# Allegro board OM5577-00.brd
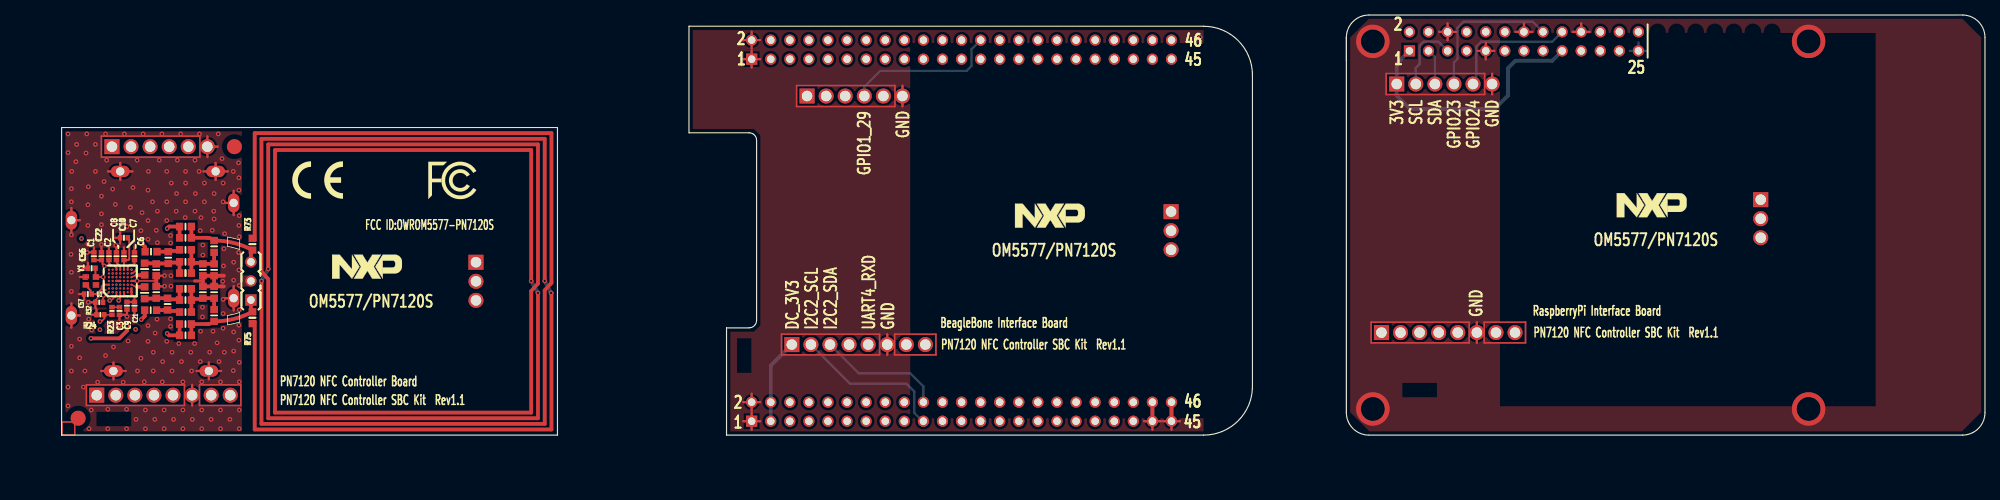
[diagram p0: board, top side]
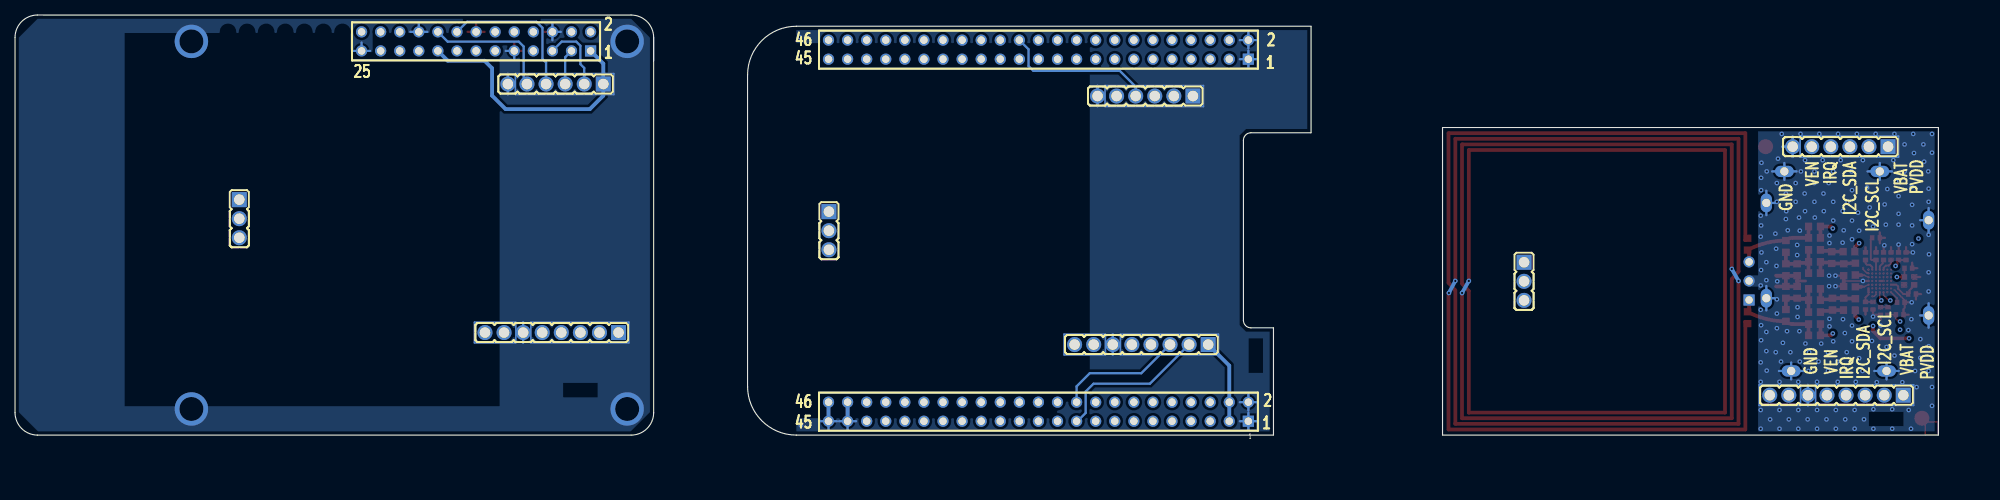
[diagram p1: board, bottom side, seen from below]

Outline 256 x 56 mm; copper layers: TOP, IS1, IS2, BOTTOM. Coordinates in mm from the lower left corner of the outline.
Outline path: 171,53 arc(171.88,55.12) 174,56 253,56 arc(255.12,55.12) 256,53 256,3 arc(255.12,0.88) 253,0 174,0 arc(171.88,0.88) 171,3 171,53 ; 171,53 171,49.9 ; 0,41 66,41 66,0 0,0 0,41 ; 83.5,54.5 83.5,40.3 91.5,40.3 arc(92.21,40.01) 92.5,39.3 92.5,15.3 arc(92.21,14.59) 91.5,14.3 88.5,14.3 88.5,0 152,0 arc(156.6,1.9) 158.5,6.5 158.5,48 arc(156.6,52.6) 152,54.5 83.5,54.5

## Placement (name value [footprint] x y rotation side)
1  BUBBLE1  [BUBBLE_DIAM8]  -6.2 8.1 0 top
2  BUBBLE2  [BUBBLE_DIAM8]  85.6 27.6 0 top
3  BUBBLE3  [BUBBLE_DIAM8]  209.95 -6.65 0 top
4  BUBBLE4(x4)  [BUBBLE_DIAM8]  175.15 -6.35 0 top
5  BUBBLE5(x4)  [BUBBLE_DIAM8]  183.35 -6.2 0 top
6  BUBBLE6(x4)  [BUBBLE_DIAM8]  191.55 -6.2 0 top
C1  1uF  [C0402]  4.3 23.85 90 top
C2  4.7uF  [C0402]  6.3 23.85 90 top
C3  1uF  [C0402]  7.7 16.55 270 top
C6  100nF  [C0402]  9.7 23.85 90 top
C7  1uF  [C0402]  8.3 23.85 90 top
C8  470nF  [C0402]  7.3 23.85 90 top
C9  100nF  [C0402]  8.7 17.25 270 top
C10  NC  [C0402]  8.3 26.3 180 top
C11  39pF/50V  [C0603]  16.49 14.8 0 top
C12  39pF/50V  [C0603]  16.49 26.3 0 top
C13  180pF  [C0603]  12.6 19.04 90 top
C14  180pF  [C0603]  12.6 22.04 90 top
C15  18pF/50V  [C0603]  16.49 18 0 top
C16  18pF/50V  [C0603]  16.49 23.1 0 top
C17  10pF/50V  [C0603]  20.3 19.04 90 top
C18  10pF/50V  [C0603]  20.3 22.04 90 top
C19  1nF/16V  [C0603]  11.85 16.65 0 top
C20  1nF/16V  [C0603]  11.9 24.45 0 top
C21  1uF  [C0402]  9.7 17.25 270 top
C22  100nF  [C0402]  5.3 23.85 90 top
C50  NC  [C0603]  18.8 19.04 90 top
C51  NC  [C0603]  18.8 22.04 90 top
C52  NC  [C0603]  16.49 27.8 0 top
C53  NC  [C0603]  16.49 13.3 0 top
C54  NC  [C0603]  16.49 19.5 0 top
C55  NC  [C0603]  16.49 21.6 0 top
C56  10pF/50V  [C0402]  4 22.25 180 top
C57  10pF/50V  [C0402]  3.5 18.8 180 top
J1  bar_2x13_FD_RASPBERRY  [BAR_2X13_FD_SPE_RASPBERRY]  179.4 51.21 0 top
J8  bar_2x23_MD_beaglebone_p8  [BAR_2X23_SPE_BEAGLEBONE]  91.84 50.11 0 top
J9  bar_2x23_MD_beaglebone_p9  [BAR_2X23_SPE_BEAGLEBONE]  91.84 1.85 0 top
L1  560nH  [SELF_0603]  11.05 18.97 270 top
L2  560nH  [SELF_0603]  11.05 22.13 90 top
L104  Antenna  [ANTENNA_4T_40X40]  23.75 20.55 180 top
NOREF  -  []  131.6 29.25 0 top
NOREF#2  -  []  211.7 30.65 0 top
NOREF#3  -  []  40.7 22.45 0 top
NOREF#4  -  []  32.1 122.75 0 top
NOREF#5  -  [unnamed#2]  23 38.45 0 top
NOREF#6  -  []  51.3 33.95 0 top
NOREF#7  -  []  33.2 34 0 top
NOREF#8  -  [unnamed#2]  2.2 2.25 0 top
R1  2K4  [R0603]  14.1 17.46 270 top
R2  2K4  [R0603]  14.2 23.66 270 top
R23  NC  [0402R]  6.7 16.55 90 top
R24  100K  [0402R]  5.15 16.05 0 top
R32  100K  [0402R]  5 17.7 0 top
R53  NC  [R0603]  16.49 16.4 0 top
R54  NC  [R0603]  16.49 24.7 0 top
R55  3R3  [R0603]  20.3 15.95 270 top
R56  3R3  [R0603]  20.3 25.15 90 top
R73  0R  [R0603]  25.4 25.45 90 top
R75  0R  [R0603]  25.4 15.65 270 top
SH1  Shield_27x22mm  [SHIELD_27X22]  1.3 35.15 270 top
TB1  NC  [BAR_1X3_MD]  25.2 18.01 90 top
TB2  FORK  [AGPS1-08-BCZ-1MM3]  4.67 5.32 0 bottom
TB3  FORK  [AGPS1-06-BCZ-1MM3]  6.7 38.45 0 bottom
TB4  FORK  [AGPS1-08-BSE]  175.67 13.67 0 bottom
TB5  FORK  [AGPS1-06-BSE]  177.7 46.8 0 bottom
TB8  FORK  [AGPS1-06-BSE]  99.22 45.2 0 bottom
TB9  FORK  [AGPS1-08-BSE]  97.19 12.07 0 bottom
TB10  FORK  [AGPS1-03-BCZ-1MM3]  55.15 23.04 270 bottom
TB11  FORK  [AGPS1-03-BSE]  147.67 29.79 270 bottom
TB12  FORK  [AGPS1-03-BSE]  226.15 31.39 270 bottom
U1  PN7120  [VFBGA49_050_SOT1320-1]  7.8 20.55 180 top
Y1  NX2016AA_27.12Mhz  [NX2016AA]  3.9 20.55 180 top

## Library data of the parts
1-3 = BUBBLE_CI: alternate symbols: (BUBBLE_DIAM4)
4 = BUBBLE_entretoise_nylon_M3x20: alternate symbols: (BUBBLE_DIAM4)
5 = BUBBLE_RONDELLE_M3_PLATE: alternate symbols: (BUBBLE_DIAM4)
6 = BUBBLE_VIS_M3X6: alternate symbols: (BUBBLE_DIAM4)
C1-C3 C6-C10 C21 C22 C56 C57 = CAP NP: User Part Number: BCNNUMBER; Tolerance: TOLERANCE
C11-C20 C50-C55 = CAP NP: Tolerance: TOLERANCE; User Part Number: PARTNUM
J1 = bar_2x13_FD_RASPBERRY_0: Tolerance: TOLERANCE; User Part Number: PARTNUM
J8 = bar_2x23_MD_beaglebone_p8: Tolerance: TOLERANCE; User Part Number: PARTNUM
J9 = bar_2x23_MD_beaglebone_p9_1: Tolerance: TOLERANCE; User Part Number: PARTNUM
L1 L2 = INDUCTOR: User Part Number: PARTNUM; Tolerance: TOLERANCE
L104 = Antenna
R1 R2 R53-R56 R73 R75 = RESISTOR: User Part Number: PARTNUM; Tolerance: TOLERANCE
R23 R24 R32 = RESISTOR_0: Tolerance: TOLERANCE; User Part Number: BCNNUMBER
SH1 = OM5782 Shield_1
TB1 TB10-TB12 = bar_1x3_MD: Tolerance: TOLERANCE; User Part Number: PARTNUM
TB2 TB4 TB9 = bar_1x8_MD: Tolerance: TOLERANCE; User Part Number: PARTNUM
TB3 TB5 TB8 = bar_1x6_MD: Tolerance: TOLERANCE; User Part Number: PARTNUM
U1 = PN7120_VFBGA49
Y1 = NX2016AA_xMhz

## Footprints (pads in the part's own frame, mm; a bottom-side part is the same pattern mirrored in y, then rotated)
0402R
  rect 0.61x0.711 smd: 1(-0.508,0) 2(0.508,0)
AGPS1-03-BCZ-1MM3
  rect 2x2 hole 1.4: 1(0,0)
  round 2 hole 1.4: 2(2.54,0) 3(5.08,0)
AGPS1-03-BSE
  rect 2x2 hole 1.4: 1(0,0)
  round 2 hole 1.4: 2(2.54,0) 3(5.08,0)
AGPS1-06-BCZ-1MM3
  rect 2x2 hole 1.4: 1(0,0)
  round 2 hole 1.4: 2(2.54,0) 3(5.08,0) 4(7.62,0) 5(10.16,0) 6(12.7,0)
AGPS1-06-BSE
  rect 2x2 hole 1.4: 1(0,0)
  round 2 hole 1.4: 2(2.54,0) 3(5.08,0) 4(7.62,0) 5(10.16,0) 6(12.7,0)
AGPS1-08-BCZ-1MM3
  rect 2x2 hole 1.4: 1(0,0)
  round 2 hole 1.4: 2(2.54,0) 3(5.08,0) 4(7.62,0) 5(10.16,0) 6(12.7,0) 7(15.24,0) 8(17.78,0)
AGPS1-08-BSE
  rect 2x2 hole 1.4: 1(0,0)
  round 2 hole 1.4: 2(2.54,0) 3(5.08,0) 4(7.62,0) 5(10.16,0) 6(12.7,0) 7(15.24,0) 8(17.78,0)
ANTENNA_4T_40X40
  round 0.5 smd: 1(-1.95,5.45) 2(-1.95,-5.45)
BAR_1X3_MD
  rect 1.49x1.49 hole 1: 1(0,0)
  round 1.49 hole 1: 2(2.54,0) 3(5.08,0)
BAR_2X13_FD_SPE_RASPBERRY
  rect 1.49x1.49 hole 1: 1(0,0)
  round 1.49 hole 1: 2(0,2.54) 3(2.54,0) 4(2.54,2.54) 5(5.08,0) 6(5.08,2.54) 7(7.62,0) 8(7.62,2.54) 9(10.16,0) 10(10.16,2.54) 11(12.7,0) 12(12.7,2.54) 13(15.24,0) 14(15.24,2.54) 15(17.78,0) 16(17.78,2.54) 17(20.32,0) 18(20.32,2.54) 19(22.86,0) 20(22.86,2.54) 21(25.4,0) 22(25.4,2.54) 23(27.94,0) 24(27.94,2.54) 25(30.48,0) 26(30.48,2.54)
BAR_2X23_SPE_BEAGLEBONE
  rect 1.49x1.49 hole 1: C1(0,0)
  round 1.49 hole 1: C2(0,2.54) C3(2.54,0) C4(2.54,2.54) C5(5.08,0) C6(5.08,2.54) C7(7.62,0) C8(7.62,2.54) C9(10.16,0) C10(10.16,2.54) C11(12.7,0) C12(12.7,2.54) C13(15.24,0) C14(15.24,2.54) C15(17.78,0) C16(17.78,2.54) C17(20.32,0) C18(20.32,2.54) C19(22.86,0) C20(22.86,2.54) C21(25.4,0) C22(25.4,2.54) C23(27.94,0) C24(27.94,2.54) C25(30.48,0) C26(30.48,2.54) C27(33.02,0) C28(33.02,2.54) C29(35.56,0) C30(35.56,2.54) C31(38.1,0) C32(38.1,2.54) C33(40.64,0) C34(40.64,2.54) C35(43.18,0) C36(43.18,2.54) C37(45.72,0) C38(45.72,2.54) C39(48.26,0) C40(48.26,2.54) C41(50.8,0) C42(50.8,2.54) C43(53.34,0) C44(53.34,2.54) C45(55.88,0) C46(55.88,2.54)
BUBBLE_DIAM8
  round 0 smd: 1(0,0)
C0402
  rect 0.61x0.711 smd: 1(-0.508,0) 2(0.508,0)
C0603
  rect 0.965x1.016 smd: 1(-0.787,0) 2(0.787,0)
NX2016AA
  rect 0.85x0.75 smd: 1(-0.675,-0.525) 3(0.675,0.525) 4(-0.675,0.525)
  custom 0.188x0.188 smd: 2(0.675,-0.525)
R0603
  rect 0.965x1.016 smd: 1(-0.787,0) 2(0.787,0)
SELF_0603
  rect 0.965x1.016 smd: 1(-0.787,0) 2(0.787,0)
SHIELD_27X22
  oval 1.5x2.5 hole 1.1: 1(0,6.5) 4(26.6,5.6) 5(26.6,18.3) 8(0,19.2)
  oval 2.5x1.5 hole 1.1: 2(6.5,0) 3(19.2,0) 6(16.9,21.6) 7(4.2,21.6)
unnamed#2
  round 2 smd: (0,0)
VFBGA49_050_SOT1320-1
  round 0.3 smd: A1(1.5,1.5) A2(1.5,1) A3(1.5,0.5) A4(1.5,0) A5(1.5,-0.5) A6(1.5,-1) A7(1.5,-1.5) B1(1,1.5) B2(1,1) B3(1,0.5) B4(1,0) B5(1,-0.5) B6(1,-1) B7(1,-1.5) C1(0.5,1.5) C2(0.5,1) C3(0.5,0.5) C4(0.5,0) C5(0.5,-0.5) C6(0.5,-1) C7(0.5,-1.5) D1(0,1.5) D2(0,1) D3(0,0.5) D4(0,0) D5(0,-0.5) D6(0,-1) D7(0,-1.5) E1(-0.5,1.5) E2(-0.5,1) E3(-0.5,0.5) E4(-0.5,0) E5(-0.5,-0.5) E6(-0.5,-1) E7(-0.5,-1.5) F1(-1,1.5) F2(-1,1) F3(-1,0.5) F4(-1,0) F5(-1,-0.5) F6(-1,-1) F7(-1,-1.5) G1(-1.5,1.5) G2(-1.5,1) G3(-1.5,0.5) G4(-1.5,0) G5(-1.5,-0.5) G6(-1.5,-1) G7(-1.5,-1.5)

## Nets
5V: J1.2(5V)
GND: C1.2 C2.2 C3.2 C6.2 C7.2 C8.2 C9.2 C10.2 C13.2 C14.1 C17.2 C18.1 C21.2 C22.2 C50.2 C51.1 C56.2 C57.2 R24.1 R32.1 SH1.1 SH1.2 SH1.3 SH1.4 SH1.5 SH1.6 SH1.7 SH1.8 TB1.2 TB2.6 TB3.6 U1.B5(TST2) U1.B6(VSS1) U1.C2(PVSS) U1.C4(VSS) U1.D4(VSS2) U1.D6(VSS3) U1.E2(DCDC_VSS) U1.F3(VSS4) U1.G4(TVSS) Y1.2(#2) Y1.4(#4)
GND_2270869: J1.6(GND#6) J1.9(GND#9) J1.14(GND#14) J1.20(GND#20) J1.25(GND#25) TB4.6 TB5.6
GND_2272419: J8.C1(GND#C1) J8.C2(GND#C2) J9.C1(GND#C1) J9.C2(GND#C2) J9.C43(GND#C43) J9.C44(GND#C44) J9.C45(GND#C45) J9.C46(GND#C46) TB8.6 TB9.6
PVDD: C2.1 C3.1 C9.1 C21.1 R23.2 TB2.1 TB3.1 U1.C7(VBAT) U1.D3(PVDD) U1.G1(VBAT2) U1.G2(VUP)
VBAT_PVDD: J9.C3(DC_3V3#C3) J9.C4(DC_3V3#C4) TB9.1
VBAT_PVDD_2271009: J1.1(3V3#1) J1.17(3V3#17) TB5.1
VDD_5V: J9.C5(VDD_5V)
_5V: J1.4(_5V)
_SYS_5V: J9.C8(_SYS_5V)
_VDD_5V: J9.C6(_VDD_5V)
ANT1: C11.1 C53.1 U1.G7(ANT1)
ANT2: C12.1 C52.1 U1.G6(ANT2)
I2C_SCL: TB2.2 TB3.2 U1.B1(I2CSCL)
I2C_SCL_2270949: J1.5(SCL) TB5.2
I2C_SCL_2272419: J9.C19(I2C2_SCL) TB9.2
I2C_SDA: TB2.3 TB3.3 U1.C1(I2CSDA)
I2C_SDA_2270933: J1.3(SDA) TB5.3
I2C_SDA_2272319: J9.C20(I2C2_SDA) TB9.3
IRQ: TB2.4 TB3.4 U1.D1(IRQ)
IRQ_2270913: J1.16(GPIO23) TB5.4
IRQ_2273337: J8.C26(GPIO1_29) TB8.4
RXN: C20.1 U1.F5(RXN)
RXP: C19.1 U1.F6(RXP)
SYS_5V: J9.C7(SYS_5V)
TX1: L1.1 U1.G3(TX1)
TX2: L2.1 U1.G5(TX2)
VEN: TB2.5 TB3.5 U1.E1(VEN)
VEN_2270923: J1.18(GPIO24) TB5.5
VEN_2272419: J9.C11(UART4_RXD) TB9.5
N2189999: C15.2 C17.1 C50.1 C54.2 R53.2 R55.1
N2190055: C16.2 C18.2 C51.2 C55.2 R54.2 R56.1
N2190079: C13.1 C15.1 C54.1 L1.2 R1.1
N2190159: C12.2 C52.2 R56.2 R73.1 TB1.3
N2190199: C11.2 C53.2 R55.2 R75.1 TB1.1
N2190513: C14.2 C16.1 C55.1 L2.2 R2.2
N2190991: L104.1 L104.2 R73.2 R75.2
N2198580: R23.1 R24.2 U1.B2(I2CADR0)
N2222470: C20.2 R2.1 R54.1
N2227379: C19.2 R1.2 R53.1
N2256986: C57.1 U1.A3(XTAL1) Y1.3(#3)
N2256988: C56.1 U1.C3(XTAL2) Y1.1(#1)
N2257197: R32.2 U1.A1(TST1)
N2257995: C1.1 C22.1 U1.C6(VDD)
N2259746: C7.1 C10.1 U1.E7(TVDD)
N2259753: C8.1 U1.D7(VDHF)
N2259760: C6.1 U1.F7(VMID)

Pads without a net: 1 1; 2 1; 3 1; 4 1; 5 1; 6 1; J1 7 8 10 11 12 13 15 19 21 22 23 24 26; J8 C3 C4 C5 C6 C7 C8 C9 C10 C11 C12 C13 C14 C15 C16 C17 C18 C19 C20 C21 C22 C23 C24 C25 C27 C28 C29 C30 C31 C32 C33 C34 C35 C36 C37 C38 C39 C40 C41 C42 C43 C44 C45 C46; J9 C9 C10 C12 C13 C14 C15 C16 C17 C18 C21 C22 C23 C24 C25 C26 C27 C28 C29 C30 C31 C32 C33 C34 C35 C36 C37 C38 C39 C40 C41 C42; TB2 7 8; TB4 1 2 3 4 5 7 8; TB8 1 2 3 5; TB9 4 7 8; TB10 1 2 3; TB11 1 2 3; TB12 1 2 3; U1 A2 A4 A5 A6 A7 B3 B4 B7 C5 D2 D5 E3 E4 E5 E6 F1 F2 F4

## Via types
v1: diameter 0.62, hole 0.31, TOP to BOTTOM, 211 vias
v2: diameter 0.28, hole 0.1, TOP to IS1, 33 vias
v3: diameter 4.445, hole 3.2, TOP to BOTTOM, 4 vias

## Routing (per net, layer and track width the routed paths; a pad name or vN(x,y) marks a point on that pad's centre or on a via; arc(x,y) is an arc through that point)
GND: length 200.9
  TOP w0.2: v1(10.05,20.55) 12.6,20.55 ; R32.1 4.49,17.99 v2(4.9,18.4) v2(5.85,19.35)
  TOP w0.3: TB3.6 19.4,39.83 ; TB3.6 20.78,38.45 ; TB3.6 19.4,37.07 ; SH1.5 19.6,9.68 ; SH1.5 17.97,8.55 ; SH1.5 19.6,7.42 ; SH1.5 21.23,8.55 ; 3.57,24.36 C1.2 4.3,25.04 ; 18.87,35.15 SH1.8 ; SH1.8 22.13,35.15 ; SH1.8 20.5,34.02 ; SH1.8 20.5,36.28 ; C7.2 8.3,25.04 ; 3.49,22.98 C56.2 2.81,22.25 ; 21.77,30.95 SH1.7 ; SH1.7 22.9,32.58 ; SH1.7 22.9,29.32 ; 7.7,15.36 C3.2 8.43,16.04 ; 4.64,16.78 R24.1 3.96,16.05 ; 4.49,16.97 R32.1 3.81,17.7 ; SH1.4 8.53,8.55 ; SH1.4 6.9,7.42 ; SH1.4 6.9,9.68 ; SH1.4 5.27,8.55 ; 7.79,25.57 C10.2 ; C10.2 7.11,26.3 ; C10.2 7.79,27.03 ; C13.2 13.48,19.82 ; 8.7,16.06 C9.2 ; 21.77,18.25 SH1.6 ; SH1.6 22.9,19.88 ; SH1.6 22.9,16.62 ; C8.2 7.3,25.04 ; SH1.2 1.3,30.28 ; SH1.2 2.43,28.65 ; SH1.2 1.3,27.02 ; C2.2 6.3,25.04 ; 2.99,18.07 C57.2 2.31,18.8 ; C14.1 13.48,21.25 ; C6.2 9.7,25.04 ; 17.37,3.94 TB2.6 17.37,6.7 ; v2(7.3,20.55) U1.D4 ; SH1.1 9.43,35.15 ; SH1.1 7.8,34.02 ; SH1.1 6.17,35.15 ; SH1.1 7.8,36.28 ; C22.2 5.3,25.04 ; SH1.3 2.43,15.95 ; SH1.3 1.3,17.58 ; SH1.3 1.3,14.32 ; U1.G4 v1(10.05,20.55) ; 2.42,21.07 Y1.2 ; 9.7,16.06 C21.2
  TOP w0.4: 18.8,20.55 17.7,20.55
  TOP w0.5: C13.2 C14.1 ; C17.2 C50.2 C51.1 C18.1 ; C17.2 21.6,19.82 ; C17.2 C18.1 ; C18.1 21.6,21.25
  IS1 w0.3: 1.3,27.52 SH1.2 ; SH1.2 1.3,29.78 ; SH1.2 2.43,28.65 ; SH1.4 6.9,9.68 ; SH1.4 5.77,8.55 ; SH1.4 8.03,8.55 ; SH1.4 6.9,7.42 ; 19.37,35.15 SH1.8 ; SH1.8 20.5,36.28 ; SH1.8 21.63,35.15 ; SH1.8 20.5,34.02 ; 19.6,7.42 SH1.5 ; SH1.5 18.47,8.55 ; SH1.5 19.6,9.68 ; SH1.5 20.73,8.55 ; TB3.6 20.73,38.45 ; TB3.6 19.4,37.12 ; TB3.6 19.4,39.78 ; 1.3,14.82 SH1.3 ; SH1.3 2.43,15.95 ; SH1.3 1.3,17.08 ; 7.8,34.02 SH1.1 ; SH1.1 6.67,35.15 ; SH1.1 7.8,36.28 ; SH1.1 8.93,35.15 ; SH1.7 22.9,32.08 ; SH1.7 21.77,30.95 ; SH1.7 22.9,29.82 ; 17.37,6.65 TB2.6 17.37,3.99 ; 21.77,18.25 SH1.6 ; SH1.6 22.9,19.38 ; SH1.6 22.9,17.12
  IS2 w0.3: 5.77,8.55 SH1.4 ; SH1.4 8.03,8.55 ; SH1.4 6.9,9.68 ; SH1.4 6.9,7.42 ; TB3.6 19.4,39.78 ; TB3.6 19.4,37.12 ; TB3.6 20.73,38.45 ; 20.5,34.02 SH1.8 ; SH1.8 21.63,35.15 ; SH1.8 19.37,35.15 ; SH1.8 20.5,36.28 ; 17.37,3.99 TB2.6 17.37,6.65 ; SH1.5 20.73,8.55 ; SH1.5 19.6,9.68 ; SH1.5 19.6,7.42 ; SH1.5 18.47,8.55 ; SH1.6 22.9,19.38 ; SH1.6 22.9,17.12 ; SH1.6 21.77,18.25 ; 21.77,30.95 SH1.7 ; SH1.7 22.9,32.08 ; SH1.7 22.9,29.82 ; 6.67,35.15 SH1.1 ; SH1.1 8.93,35.15 ; SH1.1 7.8,34.02 ; 1.3,29.78 SH1.2 1.3,27.52 ; 1.3,17.08 SH1.3 1.3,14.82
  BOTTOM w0.3: SH1.5 19.6,9.68 ; SH1.5 19.6,7.42 ; SH1.5 21.23,8.55 ; SH1.5 17.97,8.55 ; 22.9,16.62 SH1.6 ; SH1.6 22.9,19.88 ; SH1.6 21.77,18.25 ; SH1.8 22.13,35.15 ; SH1.8 20.5,34.02 ; SH1.8 20.5,36.28 ; SH1.8 18.87,35.15 ; TB3.6 19.4,39.83 ; TB3.6 20.78,38.45 ; TB3.6 19.4,37.07 ; 17.37,3.94 TB2.6 17.37,6.7 ; SH1.3 1.3,17.58 ; SH1.3 2.43,15.95 ; SH1.3 1.3,14.32 ; 1.3,27.02 SH1.2 ; SH1.2 2.43,28.65 ; SH1.2 1.3,30.28 ; 22.9,29.32 SH1.7 ; SH1.7 22.9,32.58 ; SH1.7 21.77,30.95 ; 5.27,8.55 SH1.4 ; SH1.4 6.9,9.68 ; SH1.4 8.53,8.55 ; SH1.4 6.9,7.42 ; SH1.1 7.8,36.28 ; SH1.1 9.43,35.15 ; SH1.1 7.8,34.02 ; SH1.1 6.17,35.15
  vias: v1(0.85,40.15) v1(0.85,37.65) v1(0.85,6.4) v1(0.85,3.9) v1(1.25,24.1) v1(1.3,32.85) v1(1.3,31.1) v1(1.3,26.7) v1(1.3,21.7) v1(1.3,19.15) v1(1.3,11.85) v1(1.3,8.55) v1(1.35,35.15) v1(1.9,36.45) v1(2,38.75) v1(2.4,12.8) v1(2.4,10.3) v1(2.9,6.4) v1(3.1,8.55) v1(3.25,37.6) v1(3.35,40.15) v1(3.4,24.35) v1(3.55,33.1) v1(3.5,30.7) v1(3.5,27.95) v1(3.5,25.45) v1(3.55,17.7) v1(3.6,15.45) v1(3.65,0.85) v1(4,14) v1(3.95,3.35) v1(4.5,38.75) v1(4.5,35.15) v1(4.8,7.05) v1(5.3,31.85) v1(5.3,29.5) v1(5.3,28.05) v1(5.3,25.4) v1(5.65,33.8) v1(5.85,40.15) v1(5.85,10.6) v1(6,36.65) v1(6.15,3.45) v1(6.15,0.85) v1(6.8,32.8) v1(6.9,11.75) v1(7,28.05) v1(7.15,30.75) v1(7.2,25.3) v1(7.7,14.6) v1(8.2,7.05) v1(8.35,40.15) v1(8.7,27.8) v1(8.7,15.8) v1(8.65,3.45) v1(8.65,0.85) v1(8.85,12.55) v1(9.15,30.35) v1(9.5,33) v1(9.9,2.1) v1(10.05,36.65) v1(10.1,8.55) v1(10.55,27.25) v1(10.55,10.25) v1(10.7,29.65) v1(10.85,40.15) v1(11,7.1) v1(11.15,3.35) v1(11.15,0.85) v1(11.5,32.65) v1(11.5,28.6) v1(11.5,26.1) v1(11.5,14.6) v1(11.5,12.5) v1(11.55,35.15) v1(12.1,31.1) v1(12.2,11.05) v1(12.2,8.55) v1(12.45,13.6) v1(12.4,2.1) v1(12.6,27.3) v1(12.7,15.45) v1(12.75,29.85) v1(12.75,25.65) v1(13,36.65) v1(13.35,40.15) v1(13.45,9.8) v1(13.4,7.1) v1(13.7,21.25) v1(13.7,19.85) v1(13.65,3.35) v1(13.65,0.85) v1(14,35.15) v1(14,31.1) v1(14,28.6) v1(14,12.5) v1(14.5,26.6) v1(14.5,25.6) v1(14.5,15.5) v1(14.5,14.5) v1(14.6,33.6) v1(14.55,21.25) v1(14.55,19.85) v1(14.7,11.05) v1(14.7,8.55) v1(14.9,2.1) v1(15.25,29.85) v1(15.3,32.2) v1(15.4,36.65) v1(15.6,12.2) v1(15.85,40.15) v1(15.95,9.8) v1(16.15,7.1) v1(16.15,3.35) v1(16.15,0.85) v1(16.45,29) v1(16.5,35.15) v1(16.5,33.6) v1(16.5,31.1) v1(17.2,11.05) v1(17.3,8.55) v1(17.4,2.1) v1(17.7,12.2) v1(17.75,36.65) v1(17.8,32.2) v1(17.75,29.85) v1(18.3,35.15) v1(18.35,40.15) v1(18.45,27.25) v1(18.45,9.8) v1(18.5,13.85) v1(18.55,29) v1(18.65,7.1) v1(18.65,3.35) v1(18.65,0.85) v1(18.8,25.35) v1(18.8,24) v1(18.75,17.05) v1(18.75,15.75) v1(19,33.6) v1(19,31.1) v1(19.7,11.05) v1(19.9,2.1) v1(20.05,27.3) v1(20.15,13.85) v1(20.25,29.85) v1(20.3,32.2) v1(20.3,28.8) v1(20.7,12.3) v1(20.85,40.15) v1(20.95,9.8) v1(21.15,7.1) v1(21.15,3.35) v1(21.15,0.85) v1(21.35,36.85) v1(21.45,20.5) v1(21.5,33.6) v1(21.5,31.1) v1(21.5,18.1) v1(21.5,16.2) v1(21.5,14.25) v1(21.6,24.85) v1(21.55,22.55) v1(21.65,11.05) v1(21.7,26.85) v1(22.4,2.1) v1(22.85,35.15) v1(22.9,23.05) v1(22.9,20.65) v1(22.9,13.75) v1(22.9,11.2) v1(22.85,8.6) v1(23.55,36.3) v1(23.6,34.3) v1(23.6,32.65) v1(23.65,29.25) v1(23.6,27.95) v1(23.65,26.45) v1(23.55,24.35) v1(23.6,22) v1(23.65,19.95) v1(23.65,16.7) v1(23.6,14.65) v1(23.6,12.65) v1(23.65,9.7) v1(23.65,7.1) v1(23.65,3.35) v1(23.65,0.85) v2(2.95,21.3) v2(2.95,20.85) v2(3.4,21.3) v2(3.4,20.85) v2(4.3,20.25) v2(4.3,19.8) v2(4.85,20.25) v2(4.85,19.8) v2(6.8,21.55) v2(6.8,21.05) v2(7.3,19.55) v2(7.8,21.55) v2(8.3,19.55) v2(8.8,20.05)
GND_2270869: length 82.9
  TOP w0.3: J1.20 202.25,54.88 ; J1.20 201.13,53.75 ; J1.20 203.38,53.75 ; J1.9 190.68,51.21 ; J1.9 189.56,52.34 ; J1.9 189.56,50.09 ; J1.9 188.43,51.21 ; 188.37,15.05 TB4.6 188.37,12.29 ; 183.35,53.75 J1.6 ; J1.6 184.47,54.88 ; J1.6 185.6,53.75 ; J1.6 184.47,52.63 ; J1.14 195.76,53.75 ; J1.14 193.51,53.75 ; J1.14 194.63,54.88 ; 190.4,48.18 TB5.6 190.4,45.42
  IS1 w0.3: 189.56,50.14 J1.9 ; J1.9 189.56,52.29 ; J1.9 190.63,51.21 ; J1.9 188.48,51.21 ; 193.56,53.75 J1.14 ; J1.14 194.63,54.83 ; J1.14 195.71,53.75 ; 190.4,48.13 TB5.6 190.4,45.47 ; 184.47,52.68 J1.6 ; J1.6 183.4,53.75 ; J1.6 185.55,53.75 ; J1.6 184.47,54.83 ; 188.37,15 TB4.6 188.37,12.34 ; 201.18,53.75 J1.20 ; J1.20 203.33,53.75 ; J1.20 202.25,54.83
  IS2 w0.3: 188.37,12.34 TB4.6 188.37,15 ; 190.4,48.13 TB5.6 190.4,45.47 ; J1.9 189.56,52.29 ; J1.9 190.63,51.21 ; J1.9 188.48,51.21 ; J1.9 189.56,50.14 ; 183.4,53.75 J1.6 ; J1.6 184.47,54.83 ; J1.6 184.47,52.68 ; J1.6 185.55,53.75 ; J1.20 203.33,53.75 ; J1.20 201.18,53.75 ; J1.20 202.25,54.83 ; J1.14 194.63,54.83 ; J1.14 195.71,53.75 ; J1.14 193.56,53.75 ; 208.8,51.21 J1.25 ; J1.25 210.95,51.21 ; J1.25 209.88,52.29
  BOTTOM w0.3: 190.68,51.21 J1.9 189.56,50.09 ; J1.25 211,51.21 ; J1.25 208.75,51.21 ; J1.25 209.88,52.34 ; J1.6 184.47,54.88 ; J1.6 184.47,52.63 ; J1.6 183.35,53.75 ; J1.20 203.38,53.75 ; J1.20 201.13,53.75 ; J1.20 202.25,54.88 ; 188.37,15.05 TB4.6 188.37,12.29 ; 190.4,45.42 TB5.6 190.4,48.18
  vias: v3(174.53,52.48) v3(174.53,3.48) v3(232.53,52.48) v3(232.53,3.48)
GND_2272419: length 138.5
  TOP w0.3: J8.C2 91.84,53.78 ; J8.C2 91.84,51.53 ; J8.C2 90.72,52.65 ; J8.C2 92.97,52.65 ; J9.C2 91.84,5.52 ; J9.C2 90.72,4.39 ; J9.C2 92.97,4.39 ; J9.C2 91.84,3.27 ; 111.92,43.82 TB8.6 111.92,46.58 ; 145.19,0.73 J9.C43 ; J9.C43 144.06,1.85 ; J9.C43 146.31,1.85 ; J8.C1 92.97,50.11 ; J8.C1 91.84,51.24 ; J8.C1 90.72,50.11 ; J8.C1 91.84,48.99 ; J9.C1 92.97,1.85 ; J9.C1 91.84,2.98 ; J9.C1 91.84,0.73 ; J9.C1 90.72,1.85 ; 109.89,13.45 TB9.6 109.89,10.69 ; J9.C45 148.85,1.85 ; J9.C45 146.6,1.85 ; J9.C45 147.72,0.73
  TOP w0.5: J9.C44 J9.C43 ; J9.C46 J9.C45
  IS1 w0.3: 91.84,51.58 J8.C2 ; J8.C2 92.92,52.65 ; J8.C2 90.77,52.65 ; J8.C2 91.84,53.73 ; 111.92,43.87 TB8.6 111.92,46.53 ; 144.11,1.85 J9.C43 ; J9.C43 145.19,0.78 ; J9.C43 146.26,1.85 ; 147.72,0.78 J9.C45 ; J9.C45 148.8,1.85 ; J9.C45 146.65,1.85 ; J9.C1 91.84,2.93 ; J9.C1 90.77,1.85 ; J9.C1 92.92,1.85 ; J9.C1 91.84,0.78 ; J8.C1 92.92,50.11 ; J8.C1 91.84,51.19 ; J8.C1 90.77,50.11 ; J8.C1 91.84,49.04 ; J9.C2 91.84,5.47 ; J9.C2 91.84,3.32 ; J9.C2 90.77,4.39 ; J9.C2 92.92,4.39 ; 109.89,10.74 TB9.6 109.89,13.4
  IS1 w0.5: J9.C46 J9.C45 ; J9.C44 J9.C43
  IS2 w0.3: J8.C1 92.92,50.11 ; J8.C1 91.84,49.04 ; J8.C1 91.84,51.19 ; J8.C1 90.77,50.11 ; J9.C1 92.92,1.85 ; J9.C1 91.84,0.78 ; J9.C1 91.84,2.93 ; J9.C1 90.77,1.85 ; 90.77,4.39 J9.C2 ; J9.C2 91.84,5.47 ; J9.C2 92.92,4.39 ; J9.C2 91.84,3.32 ; 146.65,1.85 J9.C45 ; J9.C45 148.8,1.85 ; J9.C45 147.72,0.78 ; 90.77,52.65 J8.C2 ; J8.C2 91.84,53.73 ; J8.C2 91.84,51.58 ; J8.C2 92.92,52.65 ; 109.89,13.4 TB9.6 109.89,10.74 ; J9.C43 146.26,1.85 ; J9.C43 144.11,1.85 ; J9.C43 145.19,0.78 ; 111.92,43.87 TB8.6 111.92,46.53
  IS2 w0.5: J9.C46 J9.C45 ; J9.C44 J9.C43
  BOTTOM w0.3: J9.C2 92.97,4.39 ; J9.C2 91.84,3.27 ; J9.C2 90.72,4.39 ; J9.C2 91.84,5.52 ; J9.C45 148.85,1.85 ; J9.C45 147.72,0.73 ; J9.C45 146.6,1.85 ; 145.19,0.73 J9.C43 ; J9.C43 144.06,1.85 ; J9.C43 146.31,1.85 ; 90.72,50.11 J8.C1 ; J8.C1 91.84,48.99 ; J8.C1 92.97,50.11 ; J8.C1 91.84,51.24 ; 91.84,0.73 J9.C1 ; J9.C1 92.97,1.85 ; J9.C1 90.72,1.85 ; J9.C1 91.84,2.98 ; J8.C2 92.97,52.65 ; J8.C2 91.84,53.78 ; J8.C2 91.84,51.53 ; J8.C2 90.72,52.65 ; 111.92,46.58 TB8.6 111.92,43.82 ; 109.89,13.45 TB9.6 109.89,10.69
  BOTTOM w0.5: J9.C44 J9.C43 ; J9.C46 J9.C45
  vias: v1(151.4,1.3) v1(151.55,53.05)
PVDD: length 62.1
  TOP w0.2: R23.2 C3.1
  TOP w0.25: C2.1 6.3,22.9 6.6,22.6 7,22.6 7.3,22.3 U1.C7 ; U1.G1 9.3,18.75 9.7,18.35 C21.1 C9.1
  TOP w0.3: U1.G2 U1.G1
  TOP w0.5: v1(3.9,12.9) 7.7,12.9 8.7,13.9 v1(8.7,14.55)
  IS1 w0.25: v2(7.8,20.05) 7.8,18.65 8.19,18.27 8.19,17.71 7.84,17.36 7.76,17.36 7.7,17.3 v2(7.7,17.2) v2(7.7,16.9)
  IS1 w0.3: v2(8.7,17.9) v2(8.7,17.6) 8.7,17.2 8.4,16.9 v2(7.7,16.9) ; v1(2.65,26.2) 5.9,26.2 6.5,25.6 v2(6.5,23.5) v2(6.1,23.5)
  IS1 w0.5: v1(8.7,14.55) 8.7,14.7 7.7,15.7 v2(7.7,16.9)
  IS2 w0.5: TB3.1 2.65,34.4 v1(2.65,26.2) 2.65,14.15 v1(3.9,12.9) 3.9,6.09 TB2.1
VBAT_PVDD: length 11.4
  BOTTOM w0.5: TB9.1 94.39,9.27 J9.C4 J9.C3
VBAT_PVDD_2271009: length 34.8
  BOTTOM w0.5: J1.17 198.4,49.9 193.5,49.9 192.5,48.9 192.5,45.25 190.7,43.45 179.5,43.45 177.7,45.25 TB5.1 177.7,49.52 179.39,51.21 J1.1
ANT1: length 13.9
  TOP w0.2: U1.G7 9.3,22.07 v2(9.32,22.07)
  TOP w0.5: v1(14.05,13.55) 14.3,13.3 C53.1 C11.1
  IS1 w0.15: v2(9.32,22.07) 9.5,21.89 9.5,19.65 10.05,19.1 10.05,17.25 13.75,13.55 v1(14.05,13.55)
ANT2: length 11.5
  TOP w0.2: U1.G6 9.35,21.6 9.5,21.6 10,22.1 v2(10,22.3)
  TOP w0.5: v1(14.05,27.55) 14.3,27.8 C52.1 C12.1
  IS1 w0.15: v1(14.05,27.55) 13.8,27.55 10,23.75 v2(10,22.3)
I2C_SCL: length 42.9
  IS1 w0.15: v1(5.1,14.05) 5.65,14.6 5.65,18.05 6.65,19.05 v2(6.8,19.05)
  IS2 w0.5: TB2.2 7.21,6.24 5.1,8.35 v1(5.1,14.05) 4.35,14.8 4.35,33.95 7.05,36.65 8.3,36.65 9.24,37.59 TB3.2
I2C_SCL_2270949: length 9.8
  BOTTOM w0.3: TB5.2 180.24,48.94 180.75,49.45 180.75,51.9 181.3,52.45 183.24,52.45 J1.5
I2C_SCL_2272419: length 20.9
  BOTTOM w0.3: TB9.2 104.95,6.85 112.45,6.85 113.5,5.8 113.5,2.95 114.6,1.85 J9.C19
I2C_SDA: length 39
  TOP w0.2: U1.C1 7.3,18.65 6.6,17.95 v1(6.4,17.95)
  IS2 w0.5: TB3.3 11.78,36.68 6.25,31.15 6.25,24.55 6.5,24.3 6.5,18.05 v1(6.4,17.95) 6.4,15.75 5.9,15.25 5.9,11.7 9.75,7.85 TB2.3
I2C_SDA_2270933: length 4.8
  BOTTOM w0.3: TB5.3 182.78,50.37 J1.3
I2C_SDA_2272319: length 16.8
  BOTTOM w0.3: J9.C20 114.7,6.5 112.95,8.25 106.09,8.25 TB9.3
IRQ: length 39.8
  TOP w0.2: U1.D1 7.8,18.25 7.5,17.95 v1(7.6,17.95)
  IS2 w0.5: TB2.4 12.29,7.41 6.95,12.75 6.95,14.9 7.5,15.45 7.5,17.85 v1(7.6,17.95) 7.5,18.05 7.5,24 7.95,24.45 7.95,30.25 14.32,36.62 TB3.4
IRQ_2270913: length 20
  BOTTOM w0.3: TB5.4 185.32,49.67 185.8,50.15 185.8,54.3 186.6,55.1 195.83,55.1 J1.16
IRQ_2273337: length 20.6
  BOTTOM w0.3: TB8.4 106.84,46.44 108.95,48.55 120.45,48.55 121.1,49.2 121.1,51.43 J8.C26
RXN: length 7.5
  TOP w0.5: C20.1 11.11,25.09 10.61,25.59 10.55,25.59 v1(10.55,25.59)
  IS1 w0.15: v2(8.8,21.05) 9,21.05 9.2,21.25 9.2,21.67 8.75,22.12 8.75,24.29 10.05,25.59 v1(10.55,25.59)
RXP: length 9
  TOP w0.5: 11.06,16.65 11.06,15.86 v1(10.6,15.4)
  IS1 w0.15: v1(10.6,15.4) 9.7,16.3 9.7,18.85 9.2,19.35 9.2,20.3 8.95,20.55 8.6,20.55 8.4,20.75 8.4,21.35 8.6,21.55 v2(8.8,21.55)
TX1: length 1.8
  TOP w0.2: U1.G3 9.86,19.79
  TOP w0.25: 9.86,19.79 10.25,19.78
  TOP w0.5: 10.25,19.78 L1.1
TX2: length 1.8
  TOP w0.2: U1.G5 9.86,21.31
  TOP w0.25: 9.86,21.31 10.25,21.32
  TOP w0.5: 10.25,21.32 L2.1
VEN: length 44.7
  TOP w0.2: v2(8.8,18.5) 8.55,18.5 8.3,18.75 U1.E1
  IS1 w0.2: v1(9.85,14.1) 9.3,14.65 9.3,18 v2(8.8,18.5)
  IS2 w0.5: TB2.5 14.83,7.02 9.85,12 v1(9.85,14.1) 9.45,14.5 9.45,16.15 8.8,16.8 8.8,23.4 9.45,24.05 9.45,29.5 16.86,36.91 TB3.5
VEN_2270923: length 17.4
  BOTTOM w0.3: J1.18 198.41,52.45 188.95,52.45 188.3,51.8 188.3,47.24 TB5.5
VEN_2272419: length 11.4
  IS2 w0.3: TB9.5 105.8,10.52 105.8,3.11 J9.C11
N2189999: length 7.7
  TOP w0.5: 17.27,18.15 18.8,18.15 C50.1 C17.1 R55.1 ; 17.27,18.15 C54.2 ; 17.27,18.15 C15.2 R53.2
N2190055: length 7.8
  TOP w0.5: R56.1 C18.2 C51.2 18.8,22.95 17.27,22.95 ; 17.27,22.95 C55.2 ; 17.27,22.95 C16.2 R54.2
N2190079: length 6.3
  TOP w0.5: 15.7,18.1 14.1,18.1 R1.1 C13.1 12.56,18.21 L1.2 ; 15.7,18.1 C54.1 ; 15.7,18.1 C15.1
N2190159: length 11.7
  TOP w0.5: TB1.3 25.2,24.66 R73.1 arc(22.93,25.61) R56.2 arc(19.9,26.21) 19.42,26.3 C12.2 C52.2
N2190199: length 11.7
  TOP w0.5: C53.2 C11.2 19.42,14.8 arc(19.9,14.89) 20.3,15.16 arc(22.93,15.49) R75.1 25.2,16.44 TB1.1
N2190513: length 6.3
  TOP w0.5: 15.7,23 14.2,23 R2.2 12.65,22.88 C14.2 12.54,22.89 L2.2 ; 15.7,23 C55.1 ; 15.7,23 C16.1
N2190991: length 583.3
  TOP w0.5: v1(65.15,18.95) 65.2,18.95 65.2,0.75 25.7,0.75 L104.1 ; v1(62.5,20.55) 62.5,38 28.4,38 28.4,3 62.5,3 62.5,19.2 63.4,20.2 63.4,38.75 27.5,38.75 v1(27.5,22.15) ; v1(64.3,20.55) 64.3,39.5 26.6,39.5 26.6,21.8 27.5,20.8 27.5,2.25 63.4,2.25 v1(63.4,18.95) ; L104.2 25.7,40.25 65.2,40.25 65.2,20.3 64.3,19.3 64.3,1.5 26.6,1.5 v1(26.6,20.55)
  BOTTOM w0.5: v1(63.4,18.95) v1(62.5,20.55) ; v1(64.3,20.55) v1(65.15,18.95) ; v1(26.6,20.55) v1(27.5,22.15)
N2198580: length 7.5
  TOP w0.2: 5.67,16.04 5.7,16.01 5.7,15.55 5.3,15.15 v1(5.1,15.15) ; 5.67,16.04 R24.2 ; 5.67,16.04 R23.1
  IS1 w0.15: v1(5.1,15.15) 5.1,18 6.65,19.55 v2(6.8,19.55)
N2222470: length 3.3
  TOP w0.5: R54.1 15.7,24.55 14.2,24.55 R2.1 C20.2
N2227379: length 3.3
  TOP w0.5: C19.2 R1.2 14.1,16.55 15.7,16.55 R53.1
N2256986: length 4.6
  TOP w0.25: 3.23,20.02 3.27,20.02 3.55,19.75 3.55,19.6 3.85,19.3 3.85,18.96 C57.1 4.65,18.8 5.35,19.5 5.35,19.8 5.6,20.05 U1.A3
N2256988: length 4.4
  TOP w0.25: v1(5.53,21.07) Y1.1 4.51,21.14 C56.1
  IS1 w0.25: v2(7.3,20.05) 7.15,20.05 6.65,20.55 6.05,20.55 v1(5.53,21.07)
N2257197: length 1.7
  TOP w0.2: R32.2 5.51,18.26 U1.A1
N2257995: length 4.2
  TOP w0.25: v1(5.7,22.55) 5.45,22.8 5.45,23.19 C22.1 C1.1
  IS1 w0.25: v2(7.3,21.55) 7.3,21.95 6.7,22.55 v1(5.7,22.55)
N2259746: length 5
  TOP w0.25: C10.1 9,26.11 9,23.45 8.89,23.34 C7.1 U1.E7
N2259753: length 1.5
  TOP w0.25: C8.1 7.4,23.24 7.4,22.9 7.8,22.5 U1.D7
N2259760: length 1.9
  TOP w0.25: U1.F7 8.8,22.4 9.1,22.7 9.5,22.7 9.7,22.9 C6.1

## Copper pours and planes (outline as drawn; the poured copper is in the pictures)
GND on TOP: 0.5,0.5 0.5,40.5 24,40.5 24,21.3 25.25,21.3 25.7,20.85 25.7,20.25 25.25,19.8 24,19.8 24,0.5 ; 4 cut-outs
GND on BOTTOM: 0.5,0.5 0.5,40.5 24,40.5 24,21.3 25.25,21.3 25.7,20.85 25.7,20.25 25.25,19.8 24,19.8 24,0.5 ; 3 cut-outs
GND on IS1, IS2: 0.5,0.5 0.5,40.5 24,40.5 24,21.3 25.25,21.3 25.7,20.85 25.7,20.25 25.25,19.8 24,19.8 24,0.5
GND_2270869 on TOP, IS1: 174.05,0.5 171.5,3.06 171.5,52.99 174,55.5 253,55.5 255.5,53 255.5,3.05 252.95,0.5 ; 1 cut-out
GND_2270869 on BOTTOM: 174.05,0.5 171.5,3.06 171.5,52.99 174,55.5 253,55.5 255.5,53 255.5,3.05 252.95,0.5 ; 7 cut-outs
GND_2270869 on IS2: 174.05,0.5 171.5,3.06 171.5,52.99 174,55.5 253,55.5 255.5,53 255.5,3.05 252.95,0.5 ; 1 cut-out
GND_2272419 on TOP, IS1, IS2: 89,0.5 89,13.8 92.15,13.8 93,14.65 93,39.95 92.15,40.8 84,40.8 84,54 152,54 152,53.99 152,52.25 112.95,52.25 112.95,2.25 152,2.25 152,0.51 152,0.5
GND_2272419 on BOTTOM: 105.88,7.75 102.8,10.83 102.76,10.81 102.46,10.73 102.16,10.72 102.01,10.64 102.04,10.47 105.16,7.35 112.66,7.35 112.95,7.06 112.95,6.55 113.46,6.55 114,6.01 114,5.38 114.04,5.32 114.12,5.32 114.16,5.35 114.2,5.37 114.2,6.29 118.24,2.25 152,2.25 152,0.51 152,0.5 89,0.5 89,13.8 92.15,13.8 93,14.65 93,39.95 92.15,40.8 84,40.8 84,54 152,54 152,53.99 152,52.25 112.95,52.25 112.95,7.54 112.74,7.75

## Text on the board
Ref Des/Silkscreen Bottom: PVDD | VBAT | I2C_SCL | I2C_SDA | IRQ | VEN | GND
Ref Des/Silkscreen Top: U1 | C57 | R32 | C21 | R24 | Y1 | C56 | C1 | C22 | C2 | C8 | C10 | C7 | C6 | R73 | R75 | R23 | C3 | C9 | FCC ID:OWROM5577-PN7120S | PN7120 NFC Controller Board | PN7120 NFC Controller SBC Kit  Rev1.1 | BeagleBone Interface Board | RaspberryPi Interface Board | OM5577/PN7120S | DC_3V3 | I2C2_SCL | I2C2_SDA | UART4_RXD | GND | GPIO1_29 | 3V3 | SCL | SDA | GPIO23 | GPIO24
User.45: D1 | 2 | 1 | 10 | 9 | 46 | 45 | PWR | TP14 | 3 | 4 | TOP ASSEMBLY | P5 | U1 | U8 | P8 | P9 | Scale : 1.5/1 | NPC100 NICE DEMOBOARD V1.0 | NPC NICE DEMOBOARD V1.0 | DRILL MANUFACTURING | BeagleBone Interface Board | PN7120 NFC Controller Board | Raspberry Pi Interface Board | BOTTOM COMPONENTS | TOP COMPONENTS | OM5577-B-400 | OM5577-C-400 | PCB2379-1-300
